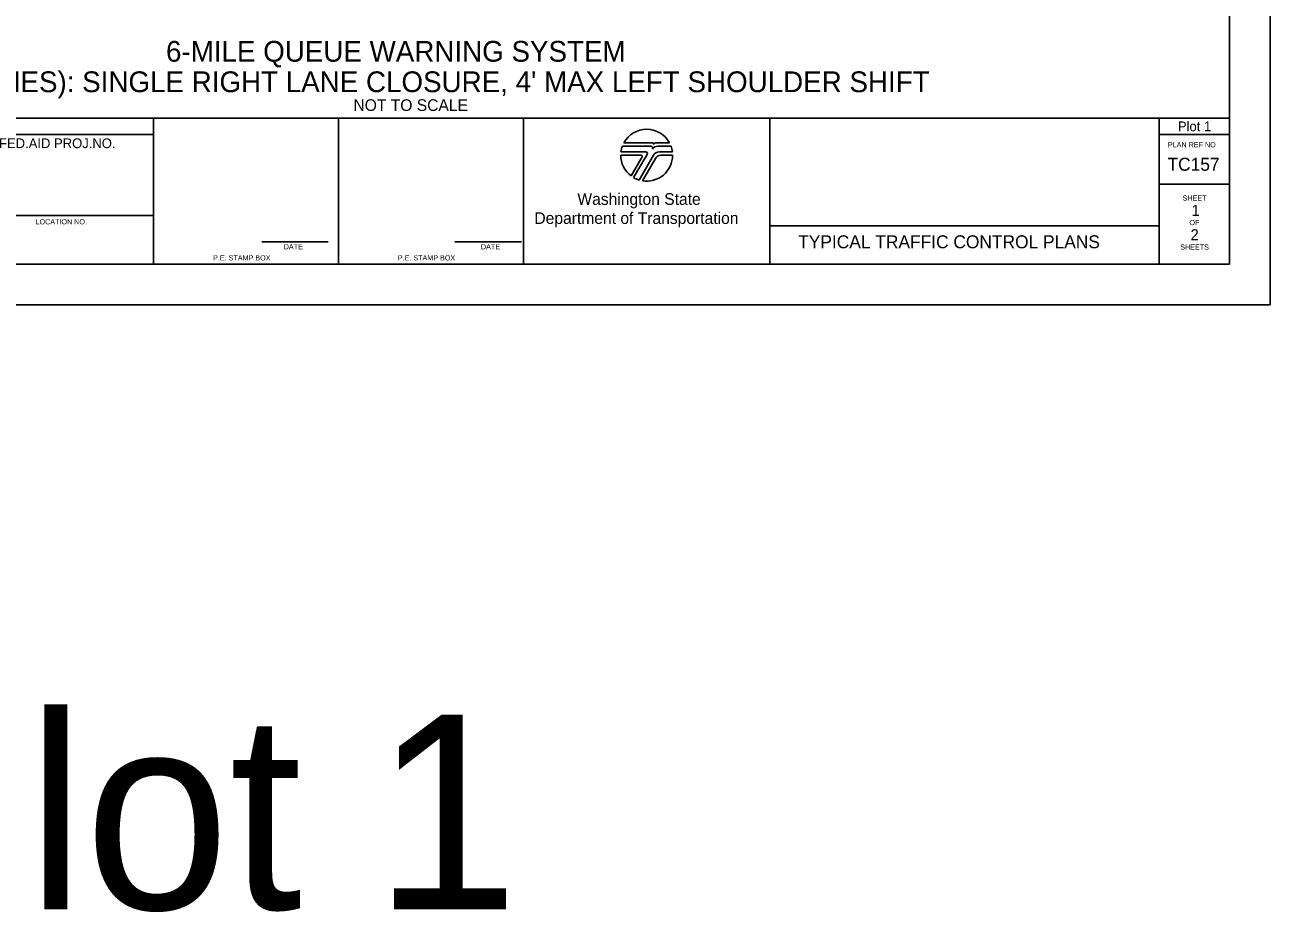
# Model space of a CAD drawing. Extents: x 99999.1 to 100055.7, y 99995 to 100010.7.
# Drawn here: x 100006.46 to 100016.06, y 99995.01 to 100001.84 of the extents above; entities that cross this region are included whole.
import ezdxf

# ---------------------------------------------------------------- set-up
doc = ezdxf.new("R2010")
doc.units = 0
for name, color, linetype in [('SH_DE_DetailHeading1Text', 7, 'Continuous'), ('SH_DE_DetailHeading3Text', 7, 'Continuous'), ('SH_GI_PlotLimits', 7, 'Continuous'), ('SH_GI_SheetBorder', 7, 'Continuous'), ('SH_GI_SheetLocationText', 7, 'Continuous'), ('SH_GI_SheetTextInCells', 7, 'Continuous'), ('SH_GI_TitleBlockText', 7, 'Continuous'), ('SH_GI_WSDOTLogo', 7, 'Continuous')]:
    doc.layers.add(name, color=color, linetype=linetype)

msp = doc.modelspace()

# ---------------------------------------------------------------- linework, layer by layer
at = {"layer": 'SH_GI_PlotLimits'}
msp.add_lwpolyline([(99999.0625, 99999.6875), (100016.0625, 99999.6875), (100016.0625, 100010.6875), (99999.0625, 100010.6875)], close=True, dxfattribs=at)
at = {"layer": 'SH_GI_SheetBorder'}
for p, q in [((100015.75, 100010.375), (100015.75, 100000)), ((100000, 100001.1259), (100015.75, 100001.1259)), ((100007.4566, 100000), (100007.4566, 100001.1259)), ((100008.8828, 100000), (100008.8828, 100001.1259)), ((100010.3089, 100001.1259), (100010.3089, 100000)), ((100012.2055, 100001.1259), (100012.2055, 100000)), ((100015.2079, 100001.1259), (100015.2079, 100000)), ((100000, 100001.0008), (100007.4566, 100001.0008)), ((100015.2079, 100001.0008), (100015.75, 100001.0008)), ((100015.2079, 100000.6176), (100015.75, 100000.6176)), ((100007.4566, 100000.3753), (100005.4466, 100000.3753)), ((100012.2055, 100000.2955), (100015.2079, 100000.2955)), ((100008.2903, 100000.1733), (100008.802, 100000.1733)), ((100009.7797, 100000.1733), (100010.2914, 100000.1733)), ((100000, 100000), (100015.75, 100000))]:
    msp.add_line(p, q, dxfattribs=at)
at = {"layer": 'SH_GI_WSDOTLogo'}
for p, q in [((100011.059, 100000.8661), (100011.2496, 100000.8661)), ((100011.2894, 100000.9094), (100011.0697, 100000.9094)), ((100011.303, 100000.9354), (100011.0815, 100000.9354)), ((100011.433, 100000.9354), (100011.3351, 100000.9354)), ((100011.343, 100000.9094), (100011.3429, 100000.9094)), ((100011.4448, 100000.9094), (100011.343, 100000.9094)), ((100011.3558, 100000.8661), (100011.4555, 100000.8661)), ((100011.0572, 100000.84), (100011.2148, 100000.84)), ((100011.222, 100000.8277), (100011.1364, 100000.6807)), ((100011.261, 100000.8464), (100011.1567, 100000.6672)), ((100011.1989, 100000.6487), (100011.3089, 100000.839)), ((100011.2244, 100000.6428), (100011.3242, 100000.8156)), ((100011.3655, 100000.8394), (100011.4572, 100000.8394))]:
    msp.add_line(p, q, dxfattribs=at)
for centre, radius, start, end in [((100011.2572, 100000.84), 0.2, 28.47865, 151.53204), ((100011.2572, 100000.84), 0.2, 159.69598, 172.50569), ((100011.2497, 100000.853), 0.0131, 329.76834, 90), ((100011.2894, 100000.8946), 0.0148, 327.8418, 89.99855), ((100011.3429, 100000.861), 0.0484, 89.99529, 147.82376), ((100011.303, 100000.9263), 0.00903, 329.87418, 90.00328), ((100011.3558, 100000.8119), 0.0542, 90, 149.99738), ((100011.3352, 100000.9066), 0.0287, 90.00721, 148.16763), ((100011.2572, 100000.84), 0.2, 7.49431, 20.29406), ((100011.2572, 100000.84), 0.2, 179.99864, 232.84327), ((100011.2149, 100000.8318), 0.0082, 329.74356, 90), ((100011.2572, 100000.84), 0.2, 260.54554, 359.80857), ((100011.3654, 100000.7918), 0.0476, 90, 150.05432), ((100011.2572, 100000.84), 0.2, 239.79292, 253.0448)]:
    msp.add_arc(centre, radius, start, end, dxfattribs=at)

# ---------------------------------------------------------------- texts
at = {"layer": 'SH_DE_DetailHeading1Text'}
for s, p in [('6-MILE QUEUE WARNING SYSTEM', (100007.5522, 100001.5606)), ("FREEWAY (2 LANES): SINGLE RIGHT LANE CLOSURE, 4' MAX LEFT SHOULDER SHIFT", (100004.647, 100001.3259))]:
    msp.add_text(s, height=0.16, rotation=360, dxfattribs=at).set_placement(p)
at = {"layer": 'SH_DE_DetailHeading3Text'}
msp.add_text('NOT TO SCALE', height=0.09, dxfattribs=at).set_placement((100008.9969, 100001.1809))
at = {"layer": 'SH_GI_SheetBorder'}
msp.add_text('PLAN REF NO', height=0.040032, dxfattribs=at).set_placement((100015.2747, 100000.9008))
at = {"layer": 'SH_GI_SheetLocationText'}
for height, p in [(0.075, (100015.3518, 100001.025)), (1.5, (100005.1422, 99995.0267))]:
    msp.add_text('Plot 1', height=height, dxfattribs=at).set_placement(p)
at = {"layer": 'SH_GI_SheetTextInCells'}
for s, height, p in [('FED.AID PROJ.NO.', 0.07506, (100006.2652, 100000.8945)), ('Washington State', 0.090072, (100010.7229, 100000.4571)), ('SHEET', 0.04003, (100015.3877, 100000.4896)), ('Department of Transportation', 0.090072, (100010.3916, 100000.3101)), ('LOCATION NO.', 0.040032, (100006.5465, 100000.3067)), ('OF', 0.04003, (100015.4406, 100000.3008)), ('DATE', 0.04003, (100008.4597, 100000.1141)), ('DATE', 0.04003, (100009.9794, 100000.1141)), ('SHEETS', 0.04003, (100015.3698, 100000.112)), ('P.E. STAMP BOX', 0.040032, (100007.915, 100000.0286)), ('P.E. STAMP BOX', 0.040032, (100009.339, 100000.0286))]:
    msp.add_text(s, height=height, dxfattribs=at).set_placement(p)
at = {"layer": 'SH_GI_TitleBlockText'}
for s, height, p in [('TC157', 0.1, (100015.2718, 100000.72)), ('1', 0.085, (100015.4566, 100000.3723)), ('TYPICAL TRAFFIC CONTROL PLANS', 0.1, (100012.4251, 100000.1224)), ('2', 0.085, (100015.4493, 100000.1843))]:
    msp.add_text(s, height=height, dxfattribs=at).set_placement(p)

doc.saveas('drawing.dxf')
